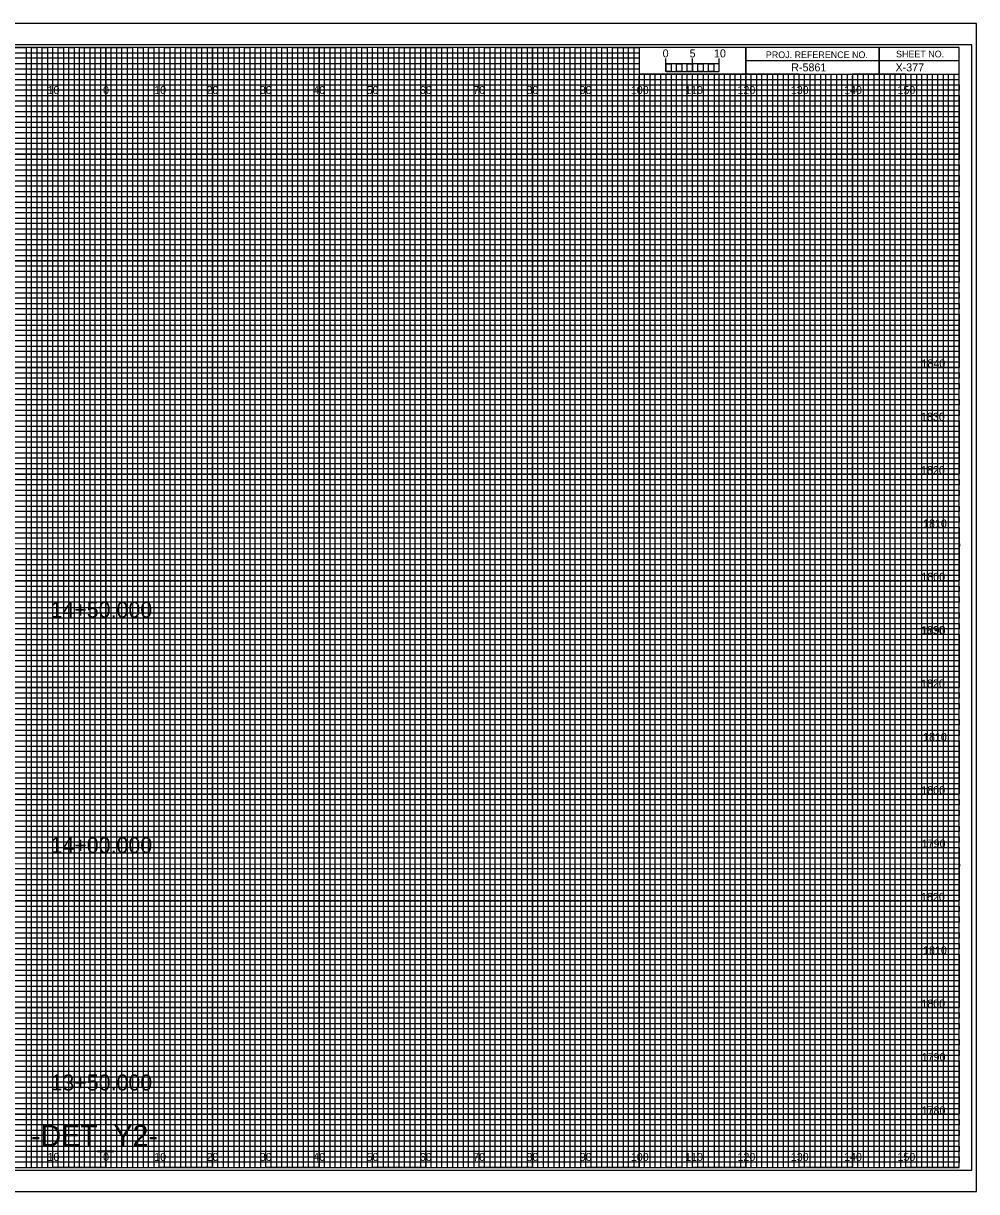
# Model space of a CAD drawing. Extents: x -13 to 323, y -5 to 874.
# Drawn here: x 144.5 to 323.3, y 435.5 to 654.5 of the extents above; entities that cross this region are included whole.
import ezdxf

# ---------------------------------------------------------------- set-up
doc = ezdxf.new("R2010")
doc.units = 0
for name, color, linetype in [('Prop Horizontal Alignment', 7, 'Continuous'), ('Prop XS Alignment Label', 7, 'Continuous'), ('Prop XS Bar Scale Labels', 7, 'Continuous'), ('Prop XS Earthwork Shape', 7, 'Continuous'), ('Prop XS Project Number', 7, 'Continuous'), ('Prop XS Sheet Number', 7, 'Continuous'), ('Raster_Level_0', 7, 'Continuous'), ('Scratch_Level_3', 7, 'Continuous'), ('Sheet Cross Section CELL', 7, 'Continuous'), ('Sheet Cross Section Grid Middle CELL', 7, 'Continuous'), ('Sheet Cross Section Grid Minor 1 CELL', 7, 'Continuous'), ('Sheet Cross Section Grid Minor 2 CELL', 7, 'Continuous'), ('Sheet Cross Section Scale CELL', 7, 'Continuous'), ('Sheet Cutting Line CELL', 7, 'Continuous'), ('Sheet DOT Grid CELL', 7, 'Continuous'), ('Sheet Plot Border Inside CELL', 7, 'Continuous'), ('Sheet Plot Border Outside CELL', 7, 'Continuous')]:
    doc.layers.add(name, color=color, linetype=linetype)

msp = doc.modelspace()

# ---------------------------------------------------------------- linework, layer by layer
at = {"layer": 'Prop XS Earthwork Shape'}
for p, q in [((150, 650), (140, 650)), ((150, 440), (150, 650)), ((170, 650), (160, 650)), ((160, 650), (160, 440)), ((170, 440), (170, 650)), ((190, 650), (180, 650)), ((180, 650), (180, 440)), ((190, 440), (190, 650)), ((210, 650), (200, 650)), ((200, 650), (200, 440)), ((210, 440), (210, 650)), ((230, 650), (220, 650)), ((220, 650), (220, 440)), ((230, 440), (230, 650)), ((250, 650), (240, 650)), ((240, 650), (240, 440)), ((250, 440), (250, 650)), ((260, 650), (260, 440)), ((270, 440), (270, 645)), ((290, 645), (280, 645)), ((280, 645), (280, 440)), ((290, 440), (290, 645)), ((310, 645), (300, 645)), ((300, 645), (300, 440)), ((310, 440), (310, 645)), ((160, 440), (150, 440)), ((180, 440), (170, 440)), ((200, 440), (190, 440)), ((220, 440), (210, 440)), ((240, 440), (230, 440)), ((260, 440), (250, 440)), ((280, 440), (270, 440)), ((300, 440), (290, 440)), ((320, 440), (310, 440)), ((320, 440), (320, 440))]:
    msp.add_line(p, q, dxfattribs=at)
for points in [[(0, 640), (320, 640), (320, 630), (0, 630)], [(0, 620), (320, 620), (320, 610), (0, 610)], [(0, 600), (320, 600), (320, 590), (0, 590)], [(0, 580), (320, 580), (320, 570), (0, 570)], [(0, 560), (320, 560), (320, 550), (0, 550)], [(0, 540), (320, 540), (320, 530), (0, 530)], [(0, 520), (320, 520), (320, 510), (0, 510)], [(0, 500), (320, 500), (320, 490), (0, 490)], [(0, 480), (320, 480), (320, 470), (0, 470)], [(0, 460), (320, 460), (320, 450), (0, 450)]]:
    msp.add_lwpolyline(points, dxfattribs=at)
at = {"layer": 'Sheet Cross Section CELL'}
for p, q in [((305, 650), (305, 645)), ((305, 645), (305, 650)), ((280, 647.5), (280, 645)), ((320, 647.49), (280, 647.49)), ((280, 645), (320, 645))]:
    msp.add_line(p, q, dxfattribs=at)
for points in [[(320, 650), (0, 650), (0, 440), (320, 440)], [(280, 650), (260, 650), (260, 645.03), (280, 645.03)], [(320, 650), (280, 650), (280, 645), (320, 645)]]:
    msp.add_lwpolyline(points, close=True, dxfattribs=at)
at = {"layer": 'Sheet Cross Section Grid Middle CELL'}
for points in [[(135, 650), (145, 650), (145, 440), (155, 440), (155, 650), (165, 650), (165, 440), (175, 440), (175, 650), (185, 650), (185, 440), (195, 440), (195, 650), (205, 650), (205, 440), (215, 440), (215, 650), (225, 650), (225, 440), (235, 440), (235, 650), (245, 650), (245, 440), (255, 440), (255, 650), (259.93, 650), (260, 650), (260, 645), (264.99, 645), (264.99, 440), (275, 440), (275, 645), (285, 645), (285, 440), (295, 440), (295, 645), (305, 645), (305, 440), (315, 440), (315, 645)], [(0, 645), (275, 645)], [(0, 625), (320, 625), (320, 635), (0, 635)], [(0, 605), (320, 605), (320, 615), (0, 615)], [(0, 585), (320, 585), (320, 595), (0, 595)], [(0, 565), (320, 565), (320, 575), (0, 575)], [(0, 545), (320, 545), (320, 555), (0, 555)], [(0, 525), (320, 525), (320, 535), (0, 535)], [(0, 505), (320, 505), (320, 515), (0, 515)], [(0, 485), (320, 485), (320, 495), (0, 495)], [(0, 465), (320, 465), (320, 475), (0, 475)], [(0, 445), (320, 445), (320, 455), (0, 455)]]:
    msp.add_lwpolyline(points, dxfattribs=at)
at = {"layer": 'Sheet Cross Section Grid Minor 1 CELL'}
for p, q in [((0, 649), (260, 649)), ((260, 649), (260, 647.98)), ((260, 647.98), (0, 647.98)), ((0, 647), (260, 647)), ((260, 647), (260, 645.89)), ((260, 645.89), (0, 645.89)), ((0, 644), (320, 644))]:
    msp.add_line(p, q, dxfattribs=at)
for points in [[(0, 643), (270, 643), (320, 643), (320, 642), (0, 642)], [(0, 641), (320, 641), (320, 639), (0, 639)], [(0, 638), (320, 638), (320, 637), (0, 636.98)], [(0, 636), (320, 636), (320, 634), (0, 634)], [(0, 633), (320, 633), (320, 632), (0, 632)], [(0, 631), (320, 631), (320, 629), (0, 629)], [(0, 628), (320, 628), (320, 627), (0, 627)], [(0, 626), (320, 626), (320, 624), (0, 624)], [(0, 623), (320, 623), (320, 622), (0, 622)], [(0, 621), (320, 621), (320, 619), (0, 619)], [(0, 618), (320, 618), (320, 617), (0, 617)], [(0, 616), (320, 616), (320, 613.95), (320, 613), (320, 612), (0, 612)], [(0, 614), (320, 614), (320, 613), (0, 613)], [(0, 611), (320, 611), (320, 609), (0, 609.03)], [(0, 609.03), (320, 609), (320, 608), (0, 608)], [(0, 607), (320, 607), (320, 606), (0, 606)], [(0, 604), (320, 604), (320, 603), (0, 603)], [(0, 602), (320, 602), (320, 601), (0, 601)], [(-0.07, 598.89), (320, 598.89), (320, 597.88), (-0.07, 597.88)], [(0, 597), (320, 597), (320, 596), (0, 596)], [(0, 594), (320, 594), (320, 593), (0, 593)], [(0, 592), (320, 592), (320, 591), (0, 591)], [(0, 589), (320, 589), (320, 588), (0, 588)], [(0, 587), (320, 587), (320, 586), (0, 586)], [(0, 584), (320, 584), (320, 583), (0, 583)], [(0, 582), (320, 582), (320, 581), (0, 581)], [(0, 579), (320, 579), (319.99, 577.98), (0, 578)], [(0, 577), (320, 577), (320, 576), (0, 576)], [(0, 574), (320, 574), (320, 573), (0, 573)], [(0, 572), (320, 572), (320, 571), (0, 571)], [(0, 569), (320, 569), (320, 568), (0, 568)], [(0, 567), (320, 567), (320, 566), (0, 566)], [(0, 564), (320, 564), (320, 563), (0, 563)], [(0, 562), (320, 562), (320, 561), (0, 561)], [(0, 559), (320, 559), (320, 558), (0, 558)], [(0, 556.99), (320.07, 556.91), (320, 556), (0, 556)], [(0, 554), (320, 554), (320, 553), (0, 553)], [(0, 552), (320, 552), (320, 551), (0, 551)], [(0, 549), (320, 549), (320, 548), (0, 548)], [(0, 547), (320, 547), (320, 546), (0, 546)], [(0, 544), (320, 544), (320, 543), (0, 543)], [(0, 542), (320, 542), (320, 541), (0, 541)], [(0, 539), (320, 539), (320, 538), (0, 538)], [(0, 537), (320, 537), (320, 536), (0, 536)], [(0, 534), (320, 534), (320, 533), (0, 533)], [(0, 532), (320, 532), (320, 531), (0, 531)], [(0, 529), (320, 529), (320, 528), (0, 528)], [(0, 527), (320, 527), (320, 526), (0, 526)], [(0, 524), (320, 524), (320, 523), (0, 523)], [(0, 522), (320, 522), (320, 521), (0, 521)], [(0, 519), (320, 519), (319.99, 517.98), (0, 518)], [(0, 517), (320, 517), (320, 516), (0, 516)], [(0, 514), (320, 514), (320, 513), (0, 513)], [(0, 512), (320, 512), (320, 511), (0, 511)], [(0, 509), (320, 509), (320, 508), (0, 508)], [(0, 507), (320, 507), (320, 506), (0, 506)], [(0, 504), (320, 504), (320, 503), (0, 503)], [(0, 502), (320, 502), (320, 501), (0, 501)], [(0, 499), (320, 499), (320, 498), (0, 498)], [(0, 496.99), (320.07, 496.91), (320, 496), (0, 496)], [(0, 494), (320, 494), (320, 493), (0, 493)], [(0, 492), (320, 492), (320, 491), (0, 491)], [(0, 489), (320, 489), (320, 488), (0, 488)], [(0, 487), (320, 487), (320, 486), (0, 486)], [(0, 484), (320, 484), (320, 483), (0, 483)], [(0, 482), (320, 482), (320, 481), (0, 481)], [(0, 479), (320, 479), (320, 478), (0, 478)], [(0, 477), (320, 477), (320, 476), (0, 476)], [(0, 474), (320, 474), (320, 473), (0, 473)], [(0, 472), (320, 472), (320, 471), (0, 471)], [(0, 469), (320, 469), (320, 468), (0, 468)], [(0, 467), (320, 467), (320, 466), (0, 466)], [(0, 464), (320, 464), (320, 463), (0, 463)], [(0, 462), (320, 462), (320, 461), (0, 461)], [(0, 459), (320, 459), (320, 458), (0, 458)], [(0, 457), (320, 457), (320, 456), (0, 456)], [(0, 454), (320, 454), (320, 453), (0, 453)], [(0, 452), (320, 452), (320, 451), (0, 451)], [(0, 449), (320, 449), (320, 448), (0, 448)], [(0, 447), (320, 447), (320, 446), (0, 446)], [(0, 444), (320, 444), (320, 443), (0, 443)], [(0, 442), (320, 442), (320, 441), (0, 441)]]:
    msp.add_lwpolyline(points, dxfattribs=at)
at = {"layer": 'Sheet Cross Section Grid Minor 2 CELL'}
for p, q in [((267, 645), (266.01, 645)), ((266.01, 645), (266.01, 440)), ((267, 440), (267, 645)), ((269, 645), (268, 645)), ((268, 645), (268, 440)), ((269, 440), (269, 645)), ((266.01, 440), (265, 440)), ((268, 440), (267, 440))]:
    msp.add_line(p, q, dxfattribs=at)
for points in [[(145, 440), (146, 440), (146, 650), (147, 650), (147, 440)], [(147, 440), (148, 440), (148, 650), (149, 650), (149, 440)], [(150, 440), (151, 440), (151, 650), (152, 650), (152, 440)], [(152, 440), (153, 440), (153, 650), (154, 650), (154, 440)], [(155, 440), (156, 440), (156, 650), (157, 650), (157, 440)], [(157, 440), (158, 440), (158, 650), (159, 650), (159, 440)], [(160, 440), (161, 440), (161, 650), (162, 650), (162, 440)], [(162, 440), (163, 440), (163, 650), (164, 650), (164, 440)], [(165, 440), (166, 440), (166, 650), (167, 650), (167, 440)], [(167, 440), (168, 440), (168, 650), (169, 650), (169, 440)], [(170, 440), (171, 440), (171, 650), (172, 650), (172, 440)], [(172, 440), (173, 440), (173, 650), (174, 650), (174, 440)], [(175, 440), (176, 440), (176, 650), (177, 650), (177, 440)], [(177, 440), (178, 440), (178, 650), (179, 650), (179, 440)], [(180, 440), (181, 440), (181, 650), (182, 650), (182, 440)], [(182, 440), (183, 440), (183, 650), (184, 650), (184, 440)], [(185, 440), (186, 440), (186, 650), (187, 650), (187, 440)], [(187, 440), (188, 440), (188, 650), (189, 650), (189, 440)], [(190, 440), (191, 440), (191, 650), (192, 650), (192, 440)], [(192, 440), (193, 440), (193, 650), (194, 650), (194, 440)], [(195, 440), (196, 440), (196, 650), (197, 650), (197, 440)], [(197, 440), (198, 440), (198, 650), (199, 650), (199, 440)], [(200, 440), (201, 440), (201, 650), (202, 650), (202, 440)], [(202, 440), (203, 440), (203, 650), (204, 650), (204, 440)], [(205, 440), (206, 440), (206, 650), (207, 650), (207, 440)], [(207, 440), (208, 440), (208, 650), (209, 650), (209, 440)], [(210, 440), (211, 440), (211, 650), (212, 650), (212, 440)], [(212, 440), (213, 440), (213, 650), (214, 650), (214, 440)], [(215, 440), (216, 440), (216, 650), (217, 650), (217, 440)], [(217, 440), (218, 440), (218, 650), (219, 650), (219, 440)], [(220, 440), (221, 440), (221, 650), (222, 650), (222, 440)], [(222, 440), (223, 440), (223, 650), (224, 650), (224, 440)], [(225, 440), (226, 440), (226, 650), (227, 650), (227, 440)], [(227, 440), (228, 440), (228, 650), (229, 650), (229, 440)], [(230, 440), (231, 440), (231, 650), (232, 650), (232, 440)], [(232, 440), (233, 440), (233, 650), (234, 650), (234, 440)], [(235, 440), (236, 440), (236, 650), (237, 650), (237, 440)], [(237, 440), (238, 440), (238, 650), (239, 650), (239, 440)], [(240, 440), (241, 440), (241, 650), (242, 650), (242, 440)], [(242, 440), (243, 440), (243, 650), (244, 650), (244, 440)], [(245, 440), (246, 440), (246, 650), (247, 650), (247, 440)], [(247, 440), (248, 440), (248, 650), (249, 650), (249, 440)], [(250, 440), (251, 440), (251, 650), (252, 650), (252, 440)], [(252, 440), (253, 440), (253, 650), (254, 650), (254, 440)], [(255, 440), (256, 440), (256, 650), (257, 650), (257, 440)], [(257, 440), (258, 440), (258, 650), (259, 650), (259, 440)], [(260, 440), (261, 440), (261, 645), (262.02, 645), (262.02, 440)], [(262, 440), (263, 440), (263, 645), (263.99, 645), (263.99, 440)], [(270, 440), (270.98, 440), (270.98, 645), (272, 645), (272, 440)], [(272, 440), (273, 440), (273, 645), (274.05, 645), (274.05, 440)], [(275, 440), (276, 440), (276, 645), (277, 645), (277, 440)], [(277, 440), (278, 440), (278, 645), (279, 645), (279, 440)], [(280, 440), (281, 440), (281, 645), (282, 645), (282, 440)], [(282, 440), (283, 440), (283, 645), (284, 645), (284, 440)], [(285, 440), (286, 440), (286, 645), (287, 645), (287, 440)], [(287, 440), (288, 440), (288, 645), (289, 645), (289, 440)], [(290, 440), (291, 440), (291, 645), (292, 645), (292, 440)], [(292, 440), (293, 440), (293, 645), (294, 645), (294, 440)], [(295, 440), (296, 440), (296, 645), (297, 645), (297, 440)], [(297, 440), (298, 440), (298, 645), (299, 645), (299, 440)], [(300, 440), (301, 440), (301, 645), (302, 645), (302, 440)], [(302, 440), (303, 440), (303, 645), (304, 645), (304, 440)], [(305, 440), (306, 440), (306, 645), (307, 645), (307, 440)], [(307, 440), (308, 440), (308, 645), (309, 645), (309, 440)], [(310, 440), (311, 440), (311, 645), (312, 645), (312, 440)], [(312, 440), (313, 440), (313, 645), (314, 645), (314, 440)], [(315, 440), (316, 440), (316, 645), (317, 645), (317, 440)], [(317, 440), (318, 440), (318, 645), (319, 645), (319, 440)]]:
    msp.add_lwpolyline(points, dxfattribs=at)
at = {"layer": 'Sheet Cross Section Scale CELL'}
for p, q in [((265, 645.49), (265, 647.9)), ((265, 646.9), (265, 647.9)), ((270, 645.49), (270, 647.9)), ((275, 645.49), (275, 647.9)), ((275, 646.9), (275, 647.9))]:
    msp.add_line(p, q, dxfattribs=at)
for points in [[(275, 646.9), (265, 646.9), (265, 645.49), (275, 645.49)], [(265, 646.9), (266, 646.9), (266, 645.49), (265, 645.49)], [(267, 646.9), (268, 646.9), (268, 645.49), (267, 645.49)], [(269, 646.9), (270, 646.9), (270, 645.49), (269, 645.49)], [(271, 646.9), (272, 646.9), (272, 645.49), (271, 645.49)], [(273, 646.9), (274, 646.9), (274, 645.49), (273, 645.49)]]:
    msp.add_lwpolyline(points, close=True, dxfattribs=at)
at = {"layer": 'Sheet Cutting Line CELL'}
for p, q in [((323.3, 654.5), (-13.4, 654.5)), ((-13.4, 435.5), (323.3, 435.5))]:
    msp.add_line(p, q, dxfattribs=at)
at = {"layer": 'Sheet DOT Grid CELL'}
for p, q in [((150, 440), (150, 650)), ((160, 440), (160, 650)), ((170, 440), (170, 650)), ((180, 440), (180, 650)), ((190, 440), (190, 650)), ((200, 440), (200, 650)), ((210, 440), (210, 650)), ((220, 440), (220, 650)), ((230, 440), (230, 650)), ((240, 440), (240, 650)), ((250, 440), (250, 650)), ((260, 440), (260, 644.69)), ((270, 440), (270, 644.69)), ((280, 440), (280, 644.69)), ((290, 440), (290, 644.69)), ((300, 440), (300, 644.69)), ((310, 440), (310, 644.69)), ((0, 640), (320, 640)), ((0, 630), (320, 630)), ((0, 620), (320, 620)), ((0, 610), (320, 610)), ((0, 600), (320, 600)), ((0, 590), (320, 590)), ((0, 580), (320, 580)), ((0, 570), (320, 570)), ((0, 560), (320, 560)), ((0, 550), (320, 550)), ((0, 540), (320, 540)), ((0, 530), (320, 530)), ((0, 520), (320, 520)), ((0, 510), (320, 510)), ((0, 500), (320, 500)), ((0, 490), (320, 490)), ((0, 480), (320, 480)), ((0, 470), (320, 470)), ((0, 460), (320, 460)), ((0, 450), (320, 450))]:
    msp.add_line(p, q, dxfattribs=at)
at = {"layer": 'Sheet Plot Border Inside CELL'}
msp.add_lwpolyline([(-10.8, 439.5), (322.4, 439.5), (322.4, 650.5), (-10.8, 650.5)], close=True, dxfattribs=at)
at = {"layer": 'Sheet Plot Border Outside CELL'}
msp.add_lwpolyline([(-13.4, 435.5), (323.3, 435.5), (323.3, 654.5), (-13.4, 654.5)], close=True, dxfattribs=at)

# ---------------------------------------------------------------- texts
at = {"layer": 'Prop Horizontal Alignment'}
for s, p in [('14+50.000', (149.59, 543.09)), ('14+00.000', (149.59, 498.95)), ('13+50.000', (149.59, 454.46))]:
    msp.add_text(s, height=3, dxfattribs=at).set_placement(p)
at = {"layer": 'Prop XS Alignment Label'}
msp.add_text('-DET_Y2-', height=4, dxfattribs=at).set_placement((145.96, 444))
at = {"layer": 'Prop XS Bar Scale Labels'}
for s, p in [('5', (269.47, 648.12)), ('10', (274.04, 648.12))]:
    msp.add_text(s, height=1.5, dxfattribs=at).set_placement(p)
at = {"layer": 'Prop XS Project Number'}
msp.add_text('R-5861', height=1.5, dxfattribs=at).set_placement((288.53, 645.5))
at = {"layer": 'Prop XS Sheet Number'}
msp.add_text('X-377', height=1.5, dxfattribs=at).set_placement((308.09, 645.5))
at = {"layer": 'Raster_Level_0'}
for s, p in [('10', (149.04, 641.25)), ('0', (159.45, 641.25)), ('0', (159.45, 641.25)), ('10', (169.04, 641.25)), ('20', (178.86, 641.25)), ('30', (188.86, 641.25)), ('40', (198.86, 641.25)), ('50', (208.86, 641.25)), ('60', (218.86, 641.25)), ('70', (228.86, 641.25)), ('80', (238.86, 641.25)), ('90', (248.86, 641.25)), ('100', (258.44, 641.25)), ('110', (268.62, 641.25)), ('120', (278.44, 641.25)), ('130', (288.44, 641.25)), ('140', (298.44, 641.25)), ('150', (308.44, 641.25)), ('10', (149.04, 441.25)), ('0', (159.45, 441.25)), ('0', (159.45, 441.25)), ('10', (169.04, 441.25)), ('20', (178.86, 441.25)), ('30', (188.86, 441.25)), ('40', (198.86, 441.25)), ('50', (208.86, 441.25)), ('60', (218.86, 441.25)), ('70', (228.86, 441.25)), ('80', (238.86, 441.25)), ('90', (248.86, 441.25)), ('100', (258.44, 441.25)), ('110', (268.62, 441.25)), ('120', (278.44, 441.25)), ('130', (288.44, 441.25)), ('140', (298.44, 441.25)), ('150', (308.44, 441.25))]:
    msp.add_text(s, height=1.5, dxfattribs=at).set_placement(p)
at = {"layer": 'Scratch_Level_3'}
for s, p in [('1840', (312.95, 590)), ('1830', (312.86, 580)), ('1820', (312.87, 570)), ('1810', (313.25, 560)), ('1800', (312.92, 550)), ('1830', (312.86, 540)), ('1790', (313, 540)), ('1820', (312.87, 530)), ('1810', (313.25, 520)), ('1800', (312.92, 510)), ('1790', (313, 500)), ('1820', (312.87, 490)), ('1810', (313.25, 480)), ('1800', (312.92, 470)), ('1790', (313, 460)), ('1780', (312.98, 450))]:
    msp.add_text(s, height=1.5, dxfattribs=at).set_placement(p)
at = {"layer": 'Sheet Cross Section CELL'}
for s, p in [('PROJ. REFERENCE NO.', (283.77, 647.99)), ('SHEET NO.', (308.19, 648.12))]:
    msp.add_text(s, height=1.25, dxfattribs=at).set_placement(p)
at = {"layer": 'Sheet Cross Section Scale CELL'}
msp.add_text('0', height=1.5, dxfattribs=at).set_placement((264.41, 648.12))

doc.saveas('drawing.dxf')
